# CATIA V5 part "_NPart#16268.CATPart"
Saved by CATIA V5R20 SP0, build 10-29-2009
Part number: Junta tórica
Revision: ANY
Definition: UNKNOWN
Nomenclature: Junta tórica
Source: Unknown
Bounding box of the stored display mesh (mm): x -10.34 to 10.34, y -1 to 1, z -10.5 to 10.5
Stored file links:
  C:\Users\Utente\Desktop\IO LAVORO\3D X SITO CF\CUMSA\3D files AE\AE 062430\_NPart#16268.CATPart
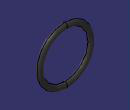
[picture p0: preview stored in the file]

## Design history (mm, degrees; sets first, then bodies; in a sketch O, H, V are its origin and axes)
Body1 "Revolución1" (main body)
  Solid1: solid without history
